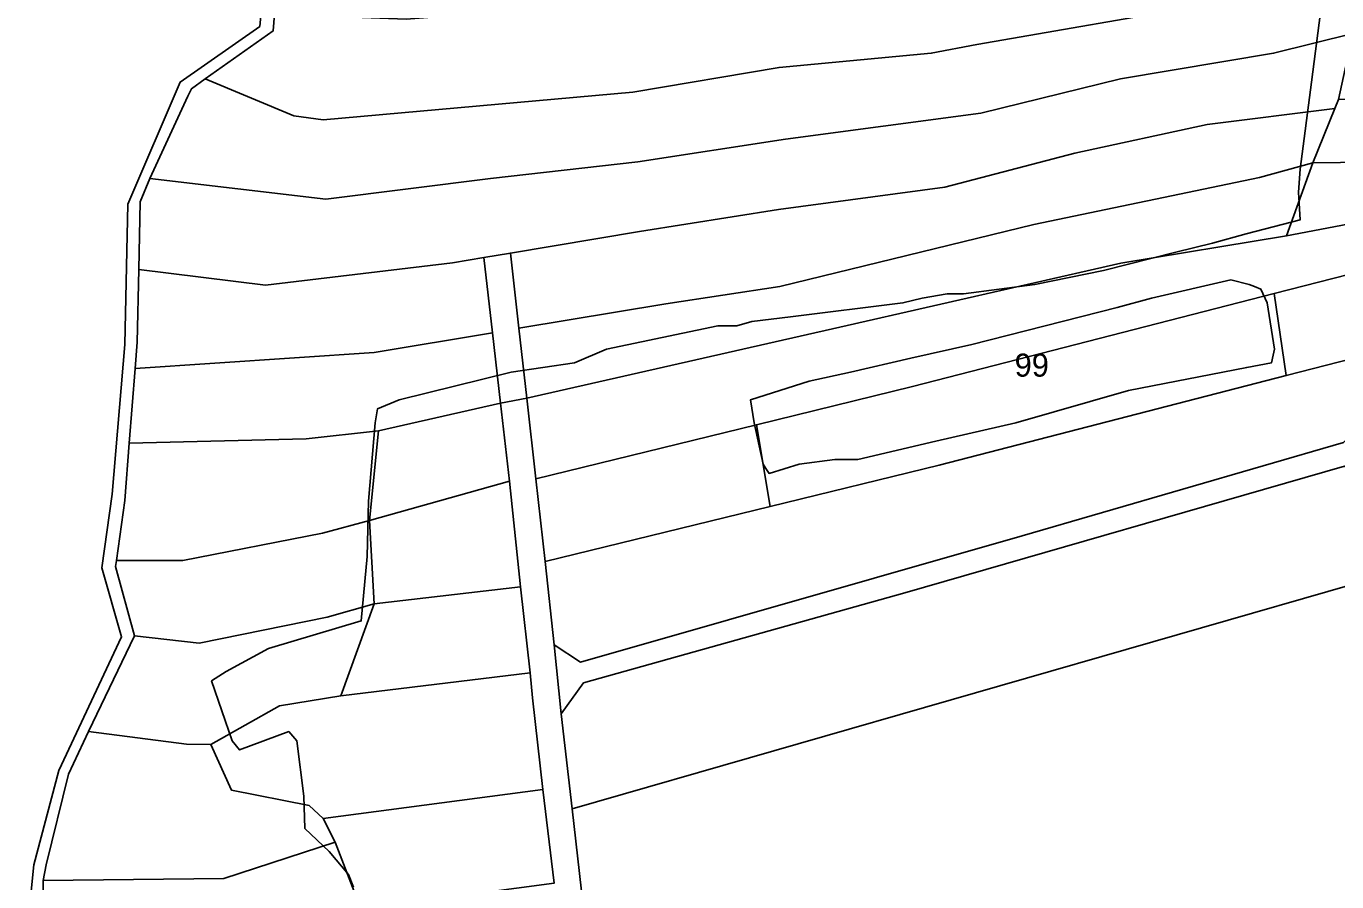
# Model space of a CAD drawing. Extents: x -541351 to -537540, y -1162694 to -1159725.
# Drawn here: x -540872.6 to -540588.2, y -1160561.6 to -1160376 of the extents above; entities that cross this region are included whole.
import ezdxf

# ---------------------------------------------------------------- set-up
doc = ezdxf.new("R2010")
doc.units = 0
for name, color, linetype in [('95560013', 7, 'Continuous'), ('95600013', 7, 'Continuous'), ('95610013', 7, 'Continuous'), ('95620013', 7, 'Continuous'), ('95630013', 7, 'Continuous'), ('95640013', 7, 'Continuous'), ('95660013', 7, 'Continuous')]:
    doc.layers.add(name, color=color, linetype=linetype)

msp = doc.modelspace()

# ---------------------------------------------------------------- linework, layer by layer
at = {"layer": '95560013'}
msp.add_lwpolyline([(-540743.76, -1160636.96), (-540754.11, -1160545.74), (-540579.05, -1160495.45), (-540572.28, -1160568.88)], close=True, dxfattribs=at)
at = {"layer": '95600013'}
for points in [[(-540601.74, -1160433.96), (-540680.28, -1160454.15), (-540714.13, -1160462.45), (-540761.96, -1160474.19), (-540763.94, -1160456.69), (-540695.98, -1160441.23), (-540635.02, -1160427.41), (-540599.1, -1160421.48), (-540566.35, -1160415.24), (-540569.52, -1160425.68)], [(-540569.52, -1160425.68), (-540576.03, -1160445.8), (-540599.16, -1160451.77), (-540601.74, -1160433.96)], [(-540752.29, -1160513.93), (-540758, -1160510.17), (-540759.94, -1160492.09), (-540711.15, -1160480.18), (-540674.45, -1160471.22), (-540599.16, -1160451.77), (-540576.03, -1160445.8), (-540580.28, -1160459.87), (-540586.72, -1160466.25), (-540656.47, -1160486.56)], [(-540761.96, -1160474.19), (-540714.13, -1160462.45), (-540711.15, -1160480.18), (-540759.94, -1160492.09)]]:
    msp.add_lwpolyline(points, close=True, dxfattribs=at)
at = {"layer": '95610013'}
for points in [[(-540593.33, -1160405.59), (-540588.56, -1160393.81), (-540587.77, -1160391.88), (-540558.89, -1160391.54), (-540563.23, -1160405.27)], [(-540593.33, -1160405.59), (-540563.23, -1160405.27), (-540566.35, -1160415.24), (-540599.1, -1160421.48)], [(-540798.1, -1160483.18), (-540796.15, -1160463.78), (-540769.64, -1160457.75), (-540767.7, -1160474.64)], [(-540756.46, -1160525.15), (-540751.64, -1160518.43), (-540681.89, -1160498.93), (-540586.46, -1160471.4), (-540581.03, -1160475.15), (-540579.05, -1160495.45), (-540754.11, -1160545.74)], [(-540767.7, -1160474.64), (-540765.32, -1160497.62), (-540797.1, -1160501.26), (-540798.1, -1160483.18)], [(-540804.31, -1160521.27), (-540797.1, -1160501.26), (-540765.32, -1160497.62), (-540763.25, -1160516.25)], [(-540817.64, -1160523.43), (-540804.31, -1160521.27), (-540763.25, -1160516.25), (-540762.69, -1160521.72), (-540760.46, -1160541.6), (-540808.15, -1160547.85), (-540811.17, -1160545.07), (-540828.05, -1160541.69), (-540832.5, -1160531.81)], [(-540805.57, -1160553.03), (-540808.15, -1160547.85), (-540760.46, -1160541.6), (-540758.03, -1160561.9), (-540800, -1160567.48)]]:
    msp.add_lwpolyline(points, close=True, dxfattribs=at)
at = {"layer": '95620013'}
for points in [[(-540590.15, -1160366.32), (-540615.31, -1160371.08), (-540666.27, -1160379.96), (-540676.17, -1160381.82), (-540709.19, -1160384.91), (-540740.96, -1160390.28), (-540808.12, -1160396.25), (-540814.52, -1160395.42), (-540833.75, -1160387.41), (-540819.02, -1160376.97), (-540818.69, -1160373.35), (-540790.11, -1160374.42), (-540683.29, -1160366.1), (-540641.4, -1160358.74), (-540581.6, -1160350.89), (-540583.96, -1160364.33)], [(-540707.82, -1160400.44), (-540739.84, -1160405.36), (-540771.86, -1160409.01), (-540807.6, -1160413.49), (-540845.75, -1160409.04), (-540837.52, -1160391.15), (-540836.74, -1160389.53), (-540833.75, -1160387.41), (-540814.52, -1160395.42), (-540808.12, -1160396.25), (-540740.96, -1160390.28), (-540709.19, -1160384.91), (-540676.17, -1160381.82), (-540666.27, -1160379.96), (-540615.31, -1160371.08), (-540590.15, -1160366.32), (-540583.96, -1160364.33), (-540584.69, -1160377.51), (-540601.9, -1160381.82), (-540635.12, -1160387.39), (-540665.45, -1160394.82)], [(-540845.75, -1160409.04), (-540807.6, -1160413.49), (-540771.86, -1160409.01), (-540739.84, -1160405.36), (-540707.82, -1160400.44), (-540665.45, -1160394.82), (-540635.12, -1160387.39), (-540601.9, -1160381.82), (-540584.69, -1160377.51), (-540587.77, -1160391.88), (-540588.56, -1160393.81), (-540616.29, -1160397.26), (-540645.03, -1160403.5), (-540673.2, -1160410.88), (-540709.36, -1160415.75), (-540739.48, -1160420.51), (-540767.5, -1160425.19), (-540773.28, -1160426.16), (-540780.07, -1160427.29), (-540820.69, -1160432.18), (-540848.18, -1160428.76), (-540847.89, -1160414.07)], [(-540653.91, -1160419.01), (-540709.05, -1160432.42), (-540733.75, -1160436.18), (-540765.66, -1160441.51), (-540767.5, -1160425.19), (-540739.48, -1160420.51), (-540709.36, -1160415.75), (-540673.2, -1160410.88), (-540645.03, -1160403.5), (-540616.29, -1160397.26), (-540588.56, -1160393.81), (-540593.33, -1160405.59), (-540604.93, -1160408.8)], [(-540763.94, -1160456.69), (-540765.66, -1160441.51), (-540733.75, -1160436.18), (-540709.05, -1160432.42), (-540653.91, -1160419.01), (-540604.93, -1160408.8), (-540593.33, -1160405.59), (-540599.1, -1160421.48), (-540635.02, -1160427.41), (-540695.98, -1160441.23)], [(-540771.4, -1160442.47), (-540797.05, -1160446.75), (-540848.95, -1160450.24), (-540848.5, -1160444.54), (-540848.18, -1160428.76), (-540820.69, -1160432.18), (-540780.07, -1160427.29), (-540773.28, -1160426.16)], [(-540711.15, -1160480.18), (-540714.13, -1160462.45), (-540680.28, -1160454.15), (-540601.74, -1160433.96), (-540599.16, -1160451.77), (-540674.45, -1160471.22)], [(-540771.4, -1160442.47), (-540769.64, -1160457.75), (-540796.15, -1160463.78), (-540811.8, -1160465.48), (-540850.22, -1160466.43), (-540848.95, -1160450.24), (-540797.05, -1160446.75)], [(-540798.1, -1160483.18), (-540808.26, -1160485.93), (-540838.62, -1160491.9), (-540853.03, -1160491.9), (-540851.19, -1160478.87), (-540850.22, -1160466.43), (-540811.8, -1160465.48), (-540796.15, -1160463.78)], [(-540807.24, -1160504.19), (-540835.04, -1160509.82), (-540849.09, -1160508.25), (-540853.21, -1160493.19), (-540853.03, -1160491.9), (-540838.62, -1160491.9), (-540808.26, -1160485.93), (-540798.1, -1160483.18), (-540797.1, -1160501.26)], [(-540807.24, -1160504.19), (-540797.1, -1160501.26), (-540804.31, -1160521.27), (-540817.64, -1160523.43), (-540832.5, -1160531.81), (-540837.78, -1160531.77), (-540859.08, -1160528.97), (-540849.09, -1160508.25), (-540835.04, -1160509.82)], [(-540832.5, -1160531.81), (-540828.05, -1160541.69), (-540811.17, -1160545.07), (-540808.15, -1160547.85), (-540805.57, -1160553.03), (-540829.71, -1160560.88), (-540868.91, -1160561.29), (-540868.25, -1160557.92), (-540863.38, -1160538.23), (-540859.08, -1160528.97), (-540837.78, -1160531.77)], [(-540829.71, -1160560.88), (-540805.57, -1160553.03), (-540800, -1160567.48), (-540825.69, -1160576.28), (-540834.33, -1160576.93), (-540868.91, -1160576.98), (-540868.91, -1160561.29)]]:
    msp.add_lwpolyline(points, close=True, dxfattribs=at)
at = {"layer": '95630013'}
for points in [[(-540872.59, -1160574.32), (-540870.95, -1160557.89), (-540865.49, -1160537.48), (-540851.88, -1160508.48), (-540856.16, -1160493.51), (-540853.95, -1160477.46), (-540851.22, -1160445), (-540850.56, -1160414.55), (-540839.17, -1160388.07), (-540821.88, -1160376.01), (-540820.09, -1160356.29)], [(-540818.69, -1160373.35), (-540819.02, -1160376.97), (-540833.75, -1160387.41), (-540836.74, -1160389.53), (-540837.52, -1160391.15), (-540845.75, -1160409.04), (-540847.89, -1160414.07), (-540848.18, -1160428.76), (-540848.5, -1160444.54), (-540848.95, -1160450.24), (-540850.22, -1160466.43), (-540851.19, -1160478.87), (-540853.03, -1160491.9), (-540853.21, -1160493.19), (-540849.09, -1160508.25), (-540859.08, -1160528.97), (-540863.38, -1160538.23), (-540868.25, -1160557.92), (-540868.91, -1160561.29), (-540868.91, -1160576.98)]]:
    msp.add_lwpolyline(points, dxfattribs=at)
at = {"layer": '95640013'}
for points in [[(-540765.66, -1160441.51), (-540763.94, -1160456.69), (-540769.64, -1160457.75), (-540771.4, -1160442.47), (-540773.28, -1160426.16), (-540767.5, -1160425.19)], [(-540586.72, -1160466.25), (-540580.28, -1160459.87), (-540581.87, -1160464.81), (-540581.03, -1160475.15), (-540586.46, -1160471.4), (-540681.89, -1160498.93), (-540751.64, -1160518.43), (-540756.46, -1160525.15), (-540758, -1160510.17), (-540752.29, -1160513.93), (-540656.47, -1160486.56)]]:
    msp.add_lwpolyline(points, close=True, dxfattribs=at)
msp.add_lwpolyline([(-540758.03, -1160561.9), (-540760.46, -1160541.6), (-540762.69, -1160521.72), (-540763.25, -1160516.25), (-540765.32, -1160497.62), (-540767.7, -1160474.64), (-540769.64, -1160457.75), (-540763.94, -1160456.69), (-540761.96, -1160474.19), (-540759.94, -1160492.09), (-540758, -1160510.17), (-540756.46, -1160525.15), (-540754.11, -1160545.74), (-540743.76, -1160636.96)], dxfattribs=at)
at = {"layer": '95660013'}
for points in [[(-540872.59, -1160574.32), (-540870.95, -1160557.89), (-540865.49, -1160537.48), (-540851.88, -1160508.48), (-540856.16, -1160493.51), (-540853.95, -1160477.46), (-540851.22, -1160445), (-540850.56, -1160414.55), (-540839.17, -1160388.07), (-540821.88, -1160376.01), (-540820.09, -1160356.29)], [(-540801.55, -1160562.78), (-540802.62, -1160560), (-540806.81, -1160555), (-540812.12, -1160550), (-540812.37, -1160543), (-540813.87, -1160531), (-540815.62, -1160529), (-540826.31, -1160533), (-540827.87, -1160531), (-540832.37, -1160518), (-540829.19, -1160516), (-540820, -1160511), (-540799.87, -1160505), (-540798.62, -1160491), (-540798.31, -1160479), (-540796.87, -1160462), (-540796.37, -1160459), (-540791.62, -1160457), (-540767.31, -1160451), (-540753.62, -1160449), (-540746.62, -1160446), (-540722.5, -1160441), (-540718.37, -1160441), (-540715.12, -1160440), (-540706.69, -1160439), (-540682.31, -1160436), (-540678.12, -1160435), (-540672.69, -1160434), (-540669.19, -1160434), (-540653.69, -1160432), (-540638.81, -1160429), (-540623.12, -1160425), (-540615.12, -1160423), (-540607.81, -1160421), (-540596.12, -1160418), (-540596.5, -1160412), (-540596.12, -1160407), (-540593.66, -1160388.11), (-540591.69, -1160373)], [(-540591.69, -1160373), (-540593.66, -1160388.11), (-540596.12, -1160407), (-540596.5, -1160412), (-540596.12, -1160418), (-540607.81, -1160421), (-540615.12, -1160423), (-540623.12, -1160425), (-540638.81, -1160429), (-540653.69, -1160432), (-540669.19, -1160434), (-540672.69, -1160434), (-540678.12, -1160435), (-540682.31, -1160436), (-540706.69, -1160439), (-540715.12, -1160440), (-540718.37, -1160441), (-540722.5, -1160441), (-540746.62, -1160446), (-540753.62, -1160449), (-540767.31, -1160451), (-540791.62, -1160457), (-540796.37, -1160459), (-540796.87, -1160462), (-540798.31, -1160479), (-540798.62, -1160491), (-540799.87, -1160505), (-540820, -1160511), (-540829.19, -1160516), (-540832.37, -1160518), (-540827.87, -1160531), (-540826.31, -1160533), (-540815.62, -1160529), (-540813.87, -1160531), (-540812.37, -1160543), (-540812.12, -1160550), (-540806.81, -1160555), (-540802.62, -1160560), (-540801.55, -1160562.78)]]:
    msp.add_lwpolyline(points, dxfattribs=at)
for points in [[(-540704.87, -1160471), (-540697.12, -1160470), (-540692.12, -1160470), (-540675.19, -1160466), (-540657.81, -1160462), (-540633.37, -1160455), (-540607.69, -1160450), (-540602.37, -1160449), (-540601.99, -1160447.33), (-540601.69, -1160446), (-540603.31, -1160436), (-540604.62, -1160433), (-540606.05, -1160432.44), (-540607.19, -1160432), (-540611.19, -1160431), (-540628.37, -1160435), (-540635.81, -1160437), (-540667.37, -1160445), (-540680.62, -1160448), (-540693.69, -1160451), (-540702.69, -1160453), (-540715.37, -1160457), (-540714.62, -1160462), (-540713.55, -1160467), (-540712.69, -1160471), (-540712.1, -1160471.89), (-540711.37, -1160473)], [(-540704.87, -1160471), (-540711.37, -1160473), (-540712.1, -1160471.89), (-540712.69, -1160471), (-540713.55, -1160467), (-540714.62, -1160462), (-540715.37, -1160457), (-540702.69, -1160453), (-540693.69, -1160451), (-540680.62, -1160448), (-540667.37, -1160445), (-540635.81, -1160437), (-540628.37, -1160435), (-540611.19, -1160431), (-540607.19, -1160432), (-540606.05, -1160432.44), (-540604.62, -1160433), (-540603.31, -1160436), (-540601.69, -1160446), (-540601.99, -1160447.33), (-540602.37, -1160449), (-540607.69, -1160450), (-540633.37, -1160455), (-540657.81, -1160462), (-540675.19, -1160466), (-540692.12, -1160470), (-540697.12, -1160470)]]:
    msp.add_lwpolyline(points, close=True, dxfattribs=at)

# ---------------------------------------------------------------- texts
msp.add_text('99', height=5, rotation=0, dxfattribs=at).set_placement((-540658.08, -1160452))

doc.saveas('drawing.dxf')
